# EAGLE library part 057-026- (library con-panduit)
CONNECTOR 20-pin series 057 contact pc board low profile headers
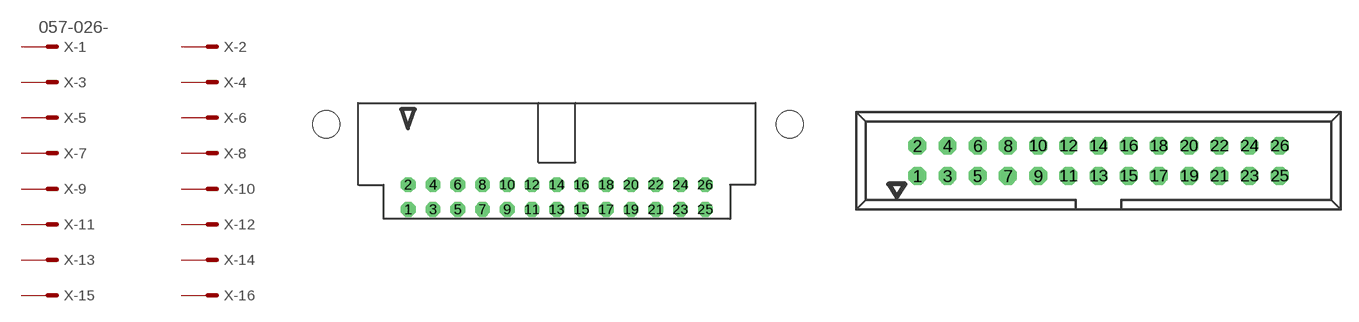
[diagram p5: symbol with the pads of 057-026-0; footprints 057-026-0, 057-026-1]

Designator prefix X; gates -1=MV -2=M -3=M -4=M -5=M -6=M -7=M -8=M -9=M -10=M -11=M -12=M -13=M -14=M -15=M -16=M -17=M -18=M -19=M -20=M -21=M -22=M -23=M -24=M -25=M -26=M

## 057-026-0 (OC_FARNELL: unknown; OC_NEWARK: unknown)  [057-026-0]
1  -1:S  pas
2  -2:S  pas
3  -3:S  pas
4  -4:S  pas
5  -5:S  pas
6  -6:S  pas
7  -7:S  pas
8  -8:S  pas
9  -9:S  pas
10  -10:S  pas
11  -11:S  pas
12  -12:S  pas
13  -13:S  pas
14  -14:S  pas
15  -15:S  pas
16  -16:S  pas
17  -17:S  pas
18  -18:S  pas
19  -19:S  pas
20  -20:S  pas
21  -21:S  pas
22  -22:S  pas
23  -23:S  pas
24  -24:S  pas
25  -25:S  pas
26  -26:S  pas

## 057-026-1 (OC_FARNELL: unknown; OC_NEWARK: unknown)  [057-026-1]
Pads as for 057-026-0

## Footprint 057-026-0 (pad centres in mm)
CONNECTOR series 057 contact pc board low profile headers angled
drill 1 octagon: 1 -15.24,-5.08; 2 -15.24,-2.54; 3 -12.7,-5.08; 4 -12.7,-2.54; 5 -10.16,-5.08; 6 -10.16,-2.54; 7 -7.62,-5.08; 8 -7.62,-2.54; 9 -5.08,-5.08; 10 -5.08,-2.54; 11 -2.54,-5.08; 12 -2.54,-2.54; 13 0,-5.08; 14 0,-2.54; 15 2.54,-5.08; 16 2.54,-2.54; 17 5.08,-5.08; 18 5.08,-2.54; 19 7.62,-5.08; 20 7.62,-2.54; 21 10.16,-5.08; 22 10.16,-2.54; 23 12.7,-5.08; 24 12.7,-2.54; 25 15.24,-5.08; 26 15.24,-2.54
hole 2.8 at -23.64,3.66
hole 2.8 at 23.89,3.66

## Footprint 057-026-1 (pad centres in mm)
CONNECTOR series 057 contact pc board low profile headers straight
drill 1 octagon: 1 -15.24,-1.27; 2 -15.24,1.27; 3 -12.7,-1.27; 4 -12.7,1.27; 5 -10.16,-1.27; 6 -10.16,1.27; 7 -7.62,-1.27; 8 -7.62,1.27; 9 -5.08,-1.27; 10 -5.08,1.27; 11 -2.54,-1.27; 12 -2.54,1.27; 13 0,-1.27; 14 0,1.27; 15 2.54,-1.27; 16 2.54,1.27; 17 5.08,-1.27; 18 5.08,1.27; 19 7.62,-1.27; 20 7.62,1.27; 21 10.16,-1.27; 22 10.16,1.27; 23 12.7,-1.27; 24 12.7,1.27; 25 15.24,-1.27; 26 15.24,1.27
